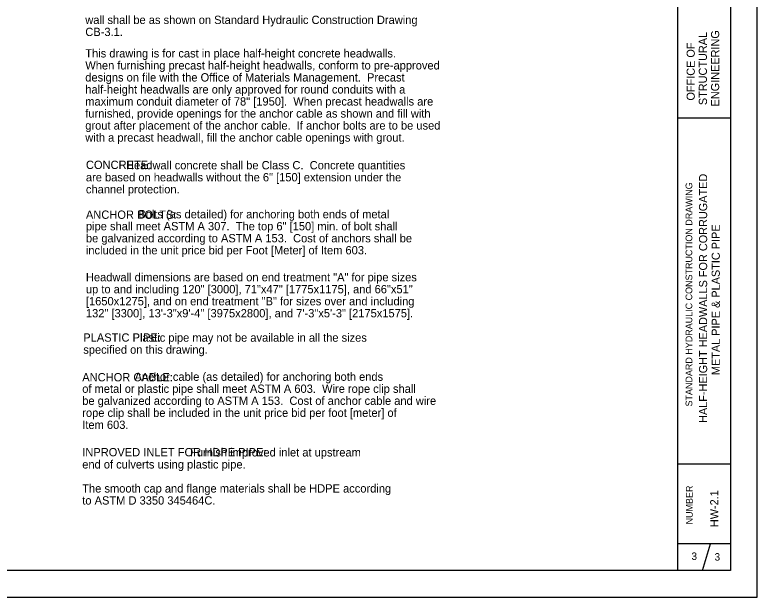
# Model space of a CAD drawing. Extents: x 1083.1 to 1117.1, y 675.4 to 741.4.
# Drawn here: x 1103.17 to 1117.13, y 675.35 to 686.3 of the extents above; entities that cross this region are included whole.
import ezdxf

# ---------------------------------------------------------------- set-up
doc = ezdxf.new("R2010")
doc.units = 0
doc.layers.add('Level 1', color=7, linetype='Continuous')

msp = doc.modelspace()

# ---------------------------------------------------------------- linework, layer by layer
at = {"layer": 'Level 1'}
for p, q in [((1117.126, 675.354), (1117.126, 697.354)), ((1115.636, 675.854), (1115.636, 696.854)), ((1116.626, 684.354), (1115.636, 684.354)), ((1115.868, 681.06), (1115.868, 681.06)), ((1116.258, 681.067), (1116.258, 681.067)), ((1116.626, 677.854), (1115.636, 677.854)), ((1116.626, 676.354), (1115.636, 676.354)), ((1116.101, 675.854), (1116.251, 676.354)), ((1083.126, 675.354), (1117.126, 675.354))]:
    msp.add_line(p, q, dxfattribs=at)
msp.add_lwpolyline([(1085.126, 696.854), (1116.626, 696.854), (1116.626, 675.854), (1085.126, 675.854)], close=True, dxfattribs=at)

# ---------------------------------------------------------------- texts
for s, height, p in [('wall shall be as shown on Standard Hydraulic Construction Drawing', 0.156, (1104.49, 686.127)), ('CB-3.1.', 0.156, (1104.49, 685.901)), ('This drawing is for cast in place half-height concrete headwalls.', 0.156, (1104.49, 685.498)), ('When furnishing precast half-height headwalls, conform to pre-approved ', 0.156, (1104.49, 685.272)), ('designs on file with the Office of Materials Management.  Precast', 0.156, (1104.49, 685.046)), ('half-height headwalls are only approved for round conduits with a', 0.156, (1104.49, 684.82)), ('maximum conduit diameter of 78" [1950].  When precast headwalls are', 0.156, (1104.49, 684.594)), ('furnished, provide openings for the anchor cable as shown and fill with ', 0.156, (1104.49, 684.368)), ('grout after placement of the anchor cable.  If anchor bolts are to be used', 0.156, (1104.49, 684.142)), ('with a precast headwall, fill the anchor cable openings with grout.', 0.156, (1104.49, 683.916)), ('CONCRETE:', 0.156, (1104.502, 683.402)), ('             Headwall concrete shall be Class C.  Concrete quantities', 0.156, (1104.502, 683.395)), ('are based on headwalls without the 6" [150] extension under the', 0.156, (1104.502, 683.169)), ('channel protection.', 0.156, (1104.502, 682.943)), ('ANCHOR BOLTS:', 0.156, (1104.502, 682.465)), ('                 Bolts (as detailed) for anchoring both ends of metal', 0.156, (1104.502, 682.475)), ('pipe shall meet ASTM A 307.  The top 6" [150] min. of bolt shall', 0.156, (1104.502, 682.249)), ('be galvanized according to ASTM A 153.  Cost of anchors shall be', 0.156, (1104.502, 682.023)), ('included in the unit price bid per Foot [Meter] of Item 603. ', 0.156, (1104.502, 681.797)), ('Headwall dimensions are based on end treatment "A" for pipe sizes', 0.156, (1104.502, 681.291)), ('up to and including 120" [3000], 71"x47" [1775x1175], and 66"x51"', 0.156, (1104.502, 681.065)), ('[1650x1275], and on end treatment "B" for sizes over and including', 0.156, (1104.502, 680.839)), ('132" [3300], 13\'-3"x9\'-4" [3975x2800], and 7\'-3"x5\'-3" [2175x1575].', 0.156, (1104.502, 680.613)), ('PLASTIC PIPE:', 0.156, (1104.452, 680.156)), ('                Plastic pipe may not be available in all the sizes', 0.156, (1104.452, 680.155)), ('specified on this drawing.       ', 0.156, (1104.452, 679.929)), ('ANCHOR CABLE:', 0.156, (1104.433, 679.41)), ('                 Anchor cable (as detailed) for anchoring both ends', 0.156, (1104.433, 679.42)), ('of metal or plastic pipe shall meet ASTM A 603.  Wire rope clip shall', 0.156, (1104.433, 679.194)), ('be galvanized according to ASTM A 153.  Cost of anchor cable and wire', 0.156, (1104.433, 678.968)), ('rope clip shall be included in the unit price bid per foot [meter] of', 0.156, (1104.433, 678.742)), ('Item 603.', 0.156, (1104.433, 678.516)), ('INPROVED INLET FOR HDPE PIPE:', 0.156, (1104.433, 678.001)), ('                                   Furnish improved inlet at upstream', 0.156, (1104.433, 677.998)), ('end of culverts using plastic pipe.', 0.156, (1104.433, 677.772)), ('The smooth cap and flange materials shall be HDPE according', 0.156, (1104.433, 677.32)), ('to ASTM D 3350 345464C.', 0.156, (1104.433, 677.094)), ('3', 0.14, (1115.891, 676.054)), ('3', 0.14, (1116.326, 676.041))]:
    msp.add_text(s, height=height, dxfattribs=at).set_placement(p)
for s, height, p in [('STRUCTURAL', 0.153, (1116.182, 684.602)), ('ENGINEERING', 0.153, (1116.412, 684.578)), ('OFFICE OF', 0.153, (1115.953, 684.688)), ('HALF-HEIGHT HEADWALLS FOR CORRUGATED', 0.153, (1116.186, 678.629)), ('STANDARD HYDRAULIC CONSTRUCTION DRAWING', 0.126, (1115.906, 678.938)), ('METAL PIPE & PLASTIC PIPE', 0.153, (1116.424, 679.528)), ('NUMBER', 0.126, (1115.915, 676.721)), ('HW-2.1', 0.153, (1116.396, 676.67))]:
    msp.add_text(s, height=height, rotation=90, dxfattribs=at).set_placement(p)

doc.saveas('drawing.dxf')
